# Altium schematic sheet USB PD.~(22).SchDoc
size A3; SheetNumber: 4; SheetTotal: 8
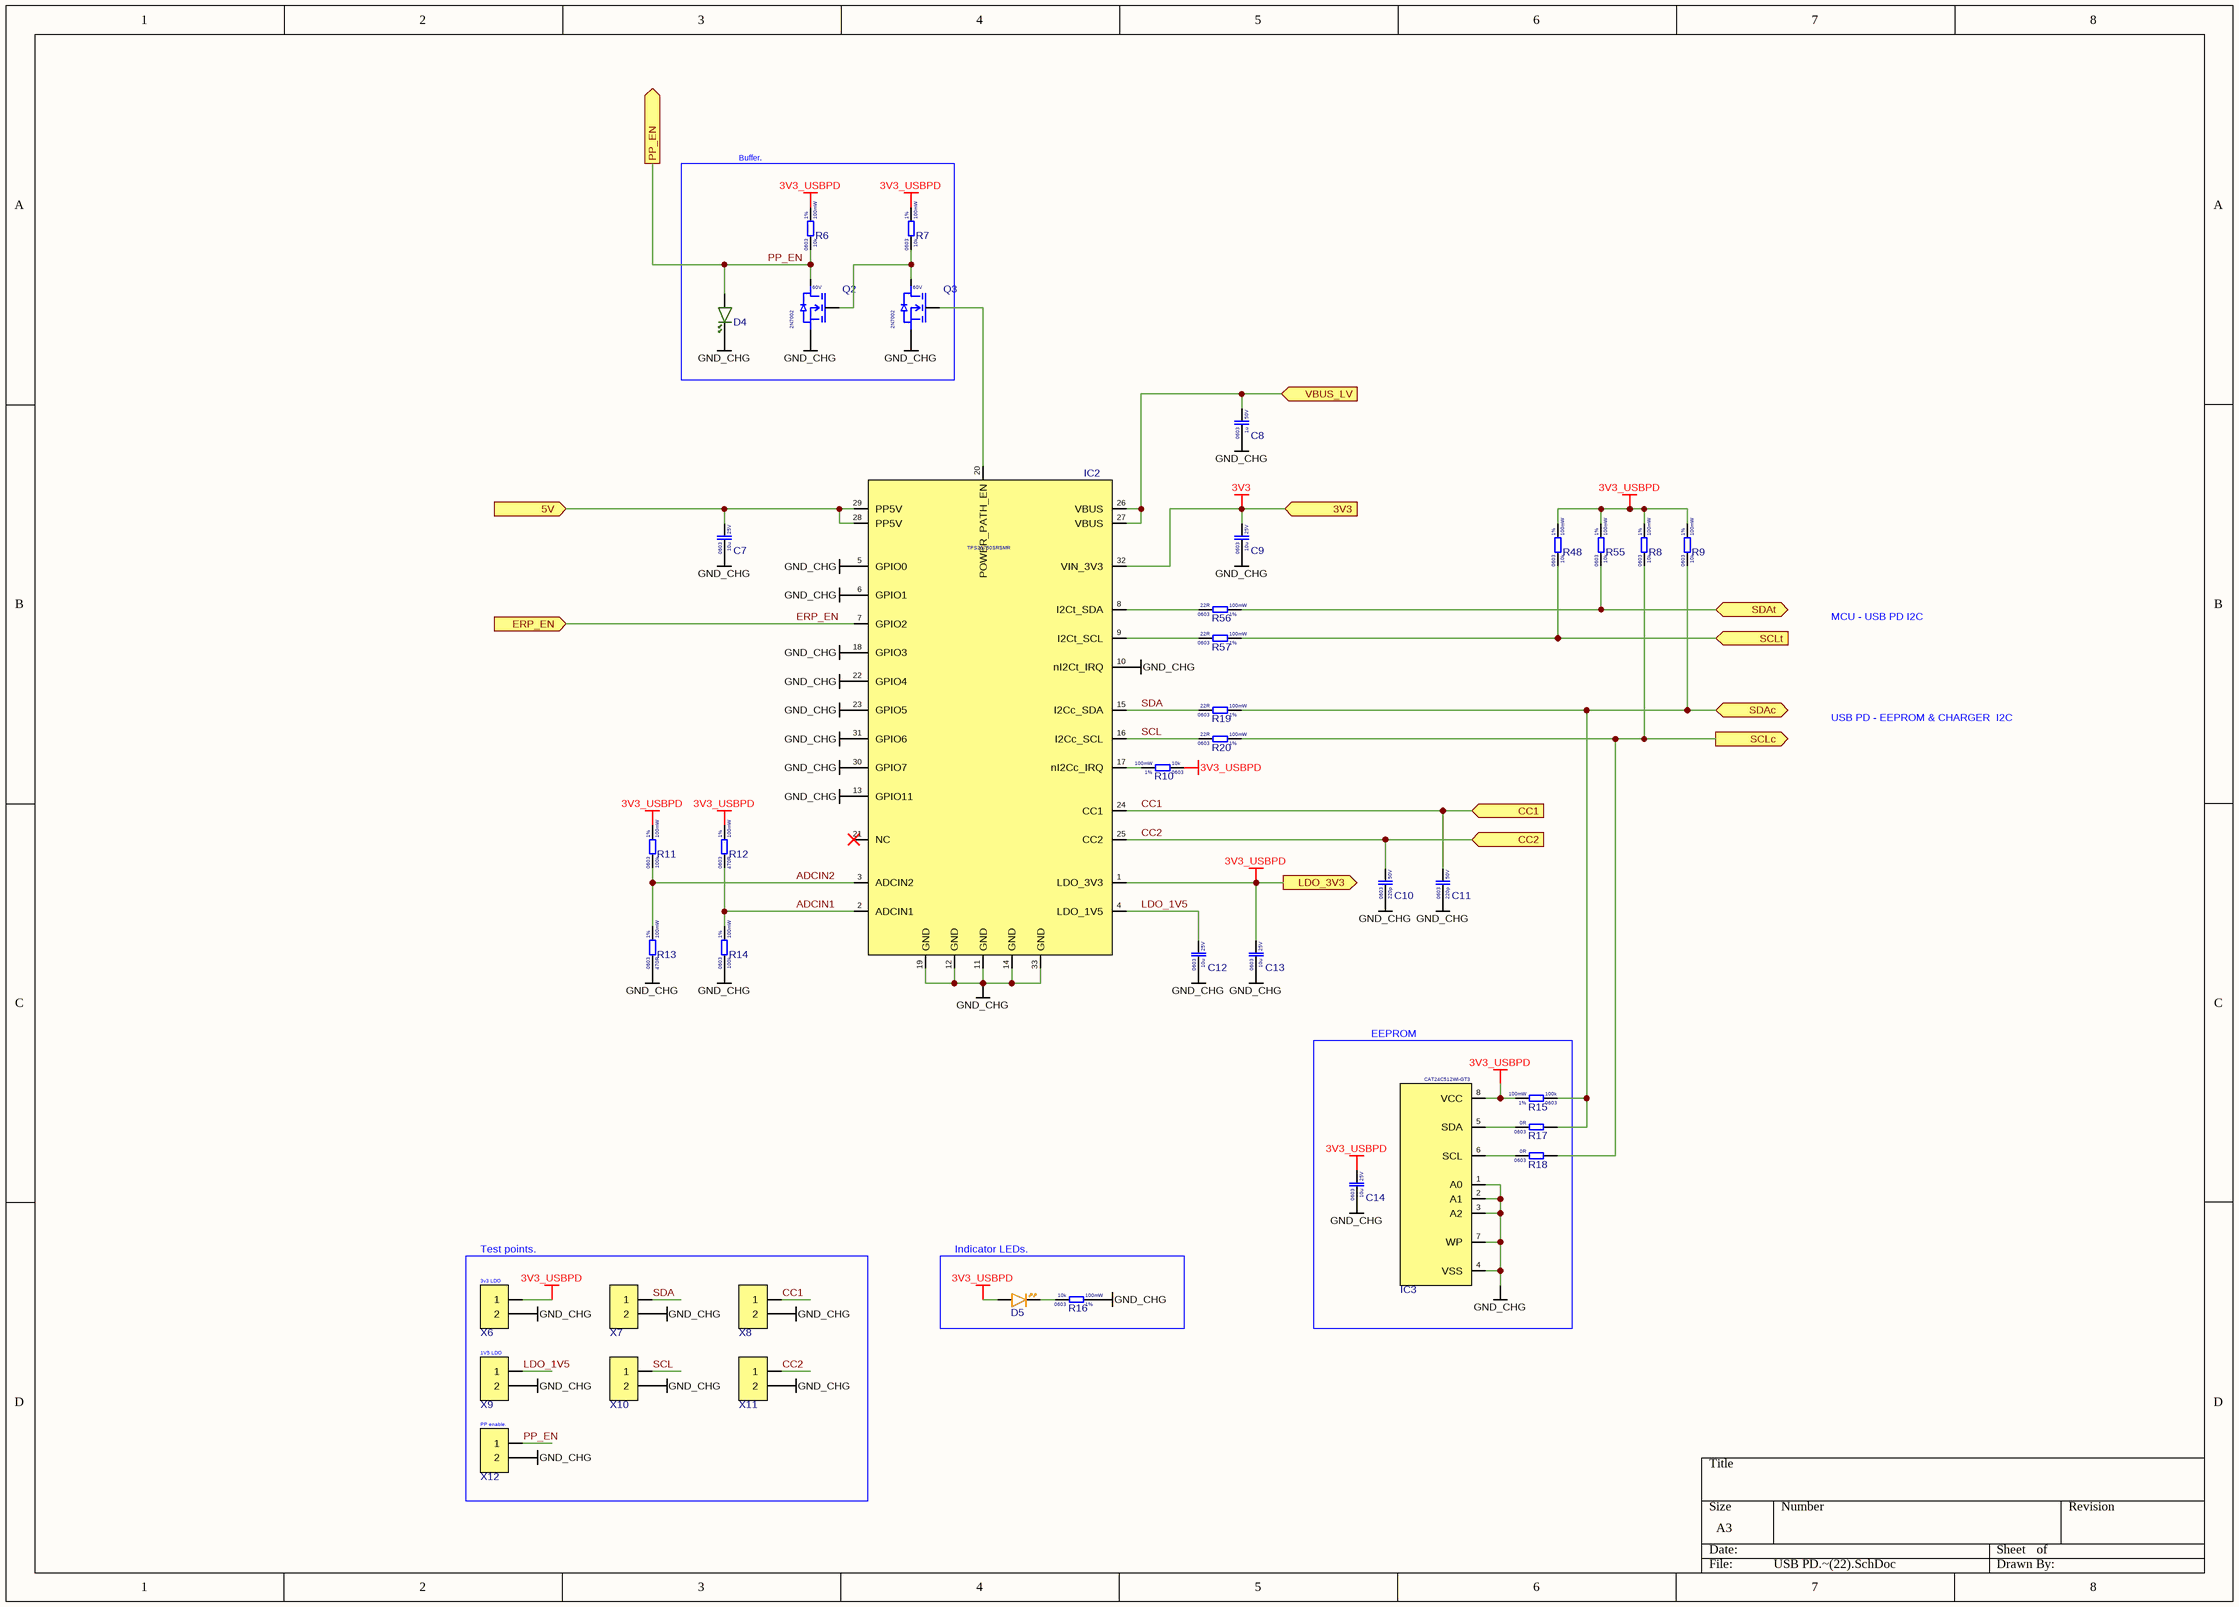
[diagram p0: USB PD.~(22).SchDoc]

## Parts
C7  Voltage Rating: 25V  Case Code (Imperial): 0603  Capacitance: 10u  [CAP 0603]  (hidden comment: CL10A106MA8NRNC)
C8  Voltage Rating: 50V  Case Code (Imperial): 0603  Capacitance: 1u  [CAP 0603]  (hidden comment: CL10A105KB8NNNC)
C9  Voltage Rating: 25V  Case Code (Imperial): 0603  Capacitance: 10u  [CAP 0603]  (hidden comment: CL10A106MA8NRNC)
C10  Voltage Rating: 50V  Case Code (Imperial): 0603  Capacitance: 220p  [CAP 0603]  (hidden comment: CL10B221KB8NNNC)
C11  Voltage Rating: 50V  Case Code (Imperial): 0603  Capacitance: 220p  [CAP 0603]  (hidden comment: CL10B221KB8NNNC)
C12  Voltage Rating: 25V  Case Code (Imperial): 0603  Capacitance: 10u  [CAP 0603]  (hidden comment: CL10A106MA8NRNC)
C13  Voltage Rating: 25V  Case Code (Imperial): 0603  Capacitance: 10u  [CAP 0603]  (hidden comment: CL10A106MA8NRNC)
C14  Voltage Rating: 25V  Case Code (Imperial): 0603  Capacitance: 10u  [CAP 0603]  (hidden comment: CL10A106MA8NRNC)
D4  PSC-1608U52GC-G4  [DIODE_0603]  (value not drawn)
D5  XL-1608UOC-06  [DIODE_0603_ORANGE]  (value not drawn)
IC2  TPS26750SRSMR  [VQFN (32) 4x4]
IC3  CAT24C512WI-GT3  [SOIC8]
Q2  Voltage: 60V  [SOT-23 GSD]  (hidden comment: 2N7002)
Q3  Voltage: 60V  [SOT-23 GSD]  (hidden comment: 2N7002)
R6  Resistance Tolerance: 1%  Resistance: 10k  Power Rating: 100mW  Case Code (Imperial): 0603  [RES_0603]  (hidden comment: 0603WAF1002T5E)
R7  Resistance Tolerance: 1%  Resistance: 10k  Power Rating: 100mW  Case Code (Imperial): 0603  [RES_0603]  (hidden comment: 0603WAF1002T5E)
R8  Resistance Tolerance: 1%  Resistance: 10k  Power Rating: 100mW  Case Code (Imperial): 0603  [RES_0603]  (hidden comment: 0603WAF1002T5E)
R9  Resistance Tolerance: 1%  Resistance: 10k  Power Rating: 100mW  Case Code (Imperial): 0603  [RES_0603]  (hidden comment: 0603WAF1002T5E)
R10  Resistance Tolerance: 1%  Resistance: 10k  Power Rating: 100mW  Case Code (Imperial): 0603  [RES_0603]  (hidden comment: 0603WAF1002T5E)
R11  Resistance Tolerance: 1%  Resistance: 100k  Power Rating: 100mW  Case Code (Imperial): 0603  [RES_0603]  (hidden comment: 0603WAF1003T5E)
R12  Resistance Tolerance: 1%  Resistance: 470R  Power Rating: 100mW  Case Code (Imperial): 0603  [RES_0603]  (hidden comment: 0603WAF4700T5E)
R13  Resistance Tolerance: 1%  Resistance: 470R  Power Rating: 100mW  Case Code (Imperial): 0603  [RES_0603]  (hidden comment: 0603WAF4700T5E)
R14  Resistance Tolerance: 1%  Resistance: 100k  Power Rating: 100mW  Case Code (Imperial): 0603  [RES_0603]  (hidden comment: 0603WAF1003T5E)
R15  Resistance Tolerance: 1%  Resistance: 100k  Power Rating: 100mW  Case Code (Imperial): 0603  [RES_0603]  (hidden comment: 0603WAF1003T5E)
R16  Resistance Tolerance: 1%  Resistance: 10k  Power Rating: 100mW  Case Code (Imperial): 0603  [RES_0603]  (hidden comment: 0603WAF1002T5E)
R17  Resistance: 0R  Case Code (Imperial): 0603  [RES_0603]  (hidden comment: 0603WAF0000T5E)
R18  Resistance: 0R  Case Code (Imperial): 0603  [RES_0603]  (hidden comment: 0603WAF0000T5E)
R19  Resistance Tolerance: 1%  Resistance: 22R  Power Rating: 100mW  Case Code (Imperial): 0603  [RES_0603]  (hidden comment: 0603WAF220JT5E)
R20  Resistance Tolerance: 1%  Resistance: 22R  Power Rating: 100mW  Case Code (Imperial): 0603  [RES_0603]  (hidden comment: 0603WAF220JT5E)
R48  Resistance Tolerance: 1%  Resistance: 10k  Power Rating: 100mW  Case Code (Imperial): 0603  [RES_0603]  (hidden comment: 0603WAF1002T5E)
R55  Resistance Tolerance: 1%  Resistance: 10k  Power Rating: 100mW  Case Code (Imperial): 0603  [RES_0603]  (hidden comment: 0603WAF1002T5E)
R56  Resistance Tolerance: 1%  Resistance: 22R  Power Rating: 100mW  Case Code (Imperial): 0603  [RES_0603]  (hidden comment: 0603WAF220JT5E)
R57  Resistance Tolerance: 1%  Resistance: 22R  Power Rating: 100mW  Case Code (Imperial): 0603  [RES_0603]  (hidden comment: 0603WAF220JT5E)
X6  ZX-PZ1.27-1-2PZZ  [Pin header 1x2 1.27mmP THT Vertical]  (value not drawn)
X7  ZX-PZ1.27-1-2PZZ  [Pin header 1x2 1.27mmP THT Vertical]  (value not drawn)
X8  ZX-PZ1.27-1-2PZZ  [Pin header 1x2 1.27mmP THT Vertical]  (value not drawn)
X9  ZX-PZ1.27-1-2PZZ  [Pin header 1x2 1.27mmP THT Vertical]  (value not drawn)
X10  ZX-PZ1.27-1-2PZZ  [Pin header 1x2 1.27mmP THT Vertical]  (value not drawn)
X11  ZX-PZ1.27-1-2PZZ  [Pin header 1x2 1.27mmP THT Vertical]  (value not drawn)
X12  ZX-PZ1.27-1-2PZZ  [Pin header 1x2 1.27mmP THT Vertical]  (value not drawn)

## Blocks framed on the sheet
Buffer.: D4 Q2 Q3 R6 R7
EEPROM: C14 IC3 R15 R17 R18
Test points.: X6-X12
Indicator LEDs.: D5 R16

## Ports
3V3 (in, see CHARGER[5C], Power distribution[6C]), 5V (in, see CHARGER[5B], Power distribution[6C]), CC1 (in, see CHARGER[6B], USB protection[3B]), CC2 (in, see CHARGER[6B], USB protection[3B]), ERP_EN (in, see CHARGER[6B], USB protection[3C]), LDO_3V3 (out, see CHARGER[6C], USB protection[3B]), PP_EN (out, see CHARGER[5B], Power path switch[5C]), SCLc (out, see CHARGER[5B], CHARGER[1D]), SCLt (in, see CHARGER[5B], CHARGER[1D]), SDAc (bidir, see CHARGER[5B], CHARGER[1D]), SDAt (bidir, see CHARGER[5B], CHARGER[1D]), VBUS_LV (in, see CHARGER[6B], USB protection[3A])

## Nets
3V3: C9.2 IC2.32(VIN_3V3) ; port 3V3
3V3_USBPD: C13.2 C14.2 D5.A IC2.1(LDO_3V3) IC3.8(VCC) R6.2 R7.2 R8.2 R9.2 R10.1 R11.2 R12.2 R15.2 R48.2 R55.2 X6.1 ; port LDO_3V3
GND_CHG: C7.1 C8.1 C9.1 C10.1 C11.1 C12.1 C13.1 C14.1 D4.K IC2.5(GPIO0) IC2.6(GPIO1) IC2.10(nI2Ct_IRQ) IC2.11(GND) IC2.12(GND) IC2.13(GPIO11) IC2.14(GND) IC2.18(GPIO3) IC2.19(GND) IC2.22(GPIO4) IC2.23(GPIO5) IC2.30(GPIO7) IC2.31(GPIO6) IC2.33(GND) IC3.1(A0) IC3.2(A1) IC3.3(A2) IC3.4(VSS) IC3.7(WP) Q2.S Q3.S R13.1 R14.1 R16.2 X6.2 X7.2 X8.2 X9.2 X10.2 X11.2 X12.2
5V: C7.2 IC2.28(PP5V) IC2.29(PP5V) ; port 5V
ADCIN1: IC2.2(ADCIN1) R12.1 R14.2
ADCIN2: IC2.3(ADCIN2) R11.1 R13.2
CC1: C11.2 IC2.24(CC1) X8.1 ; port CC1
CC2: C10.2 IC2.25(CC2) X11.1 ; port CC2
ERP_EN: IC2.7(GPIO2) ; port ERP_EN
LDO_1V5: C12.2 IC2.4(LDO_1V5) X9.1
PP_EN: D4.A Q2.D R6.1 X12.1 ; port PP_EN
SCL: IC2.16(I2Cc_SCL) R20.1 X10.1
SCLc: R8.1 R18.2 R20.2 ; port SCLc
SCLt: R48.1 R57.2 ; port SCLt
SDA: IC2.15(I2Cc_SDA) R19.1 X7.1
SDAc: R9.1 R15.1 R17.2 R19.2 ; port SDAc
SDAt: R55.1 R56.2 ; port SDAt
VBUS_LV: C8.2 IC2.26(VBUS) IC2.27(VBUS) ; port VBUS_LV
NetD5_K: D5.K R16.1
NetIC2_8: IC2.8(I2Ct_SDA) R56.1
NetIC2_9: IC2.9(I2Ct_SCL) R57.1
NetIC2_17: IC2.17(nI2Cc_IRQ) R10.2
NetIC2_20: IC2.20(POWER_PATH_EN) Q3.G
NetIC3_5: IC3.5(SDA) R17.1
NetIC3_6: IC3.6(SCL) R18.1
NetQ2_G: Q2.G Q3.D R7.1

Not connected (* = marked no-connect by the designer): IC2 21(NC)*

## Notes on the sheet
- MCU - USB PD I2C
- USB PD - EEPROM & CHARGER  I2C
- (near X6) 3v3 LDO
- (near X9) 1V5 LDO
- (near X12) PP enable.

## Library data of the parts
C7 C9 C12-C14 = CL10A106MA8NRNC: Cap 10uF 25V 0603 X5R; Manufacturer: Samsung
C8 = CL10A105KB8NNNC: Cap 1uF 50V 0603 X5R; Manufacturer: Samsung
C10 C11 = CL10B221KB8NNNC: Cap 220pF 50V 0603 X7R; Manufacturer: Samsung
D4 = PSC-1608U52GC-G4: LED Green 0603 20mA; Manufacturer: HONGLITRONIC
D5 = XL-1608UOC-06: LED Orange 0603 20mA; Manufacturer: XINGLIGHT
IC2 = TPS26750SRSMR: USB PD IC EPR 240W; Manufacturer: Texas Instruments
IC3 = CAT24C512WI-GT3: EEPROM SOIC-8; Manufacturer: OnSemi
Q2 Q3 = 2N7002: nMOS 60V 115mA SOT-23; Manufacturer: Jiangsu Changjing Electronics Technology Co., Ltd.
R6-R10 R16 R48 R55 = 0603WAF1002T5E: Res 10k 0603 1% 100mW 75V; Manufacturer: Uni-Royal
R11 R14 R15 = 0603WAF1003T5E: Res 100k 0603 1% 100mW 75V; Manufacturer: Uni-Royal
R12 R13 = 0603WAF4700T5E: Res 470R 0603 1% 100mW 75V; Manufacturer: Uni-Royal
R17 R18 = 0603WAF0000T5E: Res 0R 0603 1% 100mW 75V; Manufacturer: UNI-ROYAL
R19 R20 R56 R57 = 0603WAF220JT5E: Res 22R 0603 1% 100mW 75V; Manufacturer: Uni-Royal
X6-X12 = ZX-PZ1.27-1-2PZZ: Pin header 1x2 1.27mmP THT Vertical; Manufacturer: Megastar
